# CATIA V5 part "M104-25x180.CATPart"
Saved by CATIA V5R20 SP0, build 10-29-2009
Part number: M104-25x180
Source: Unknown
Bounding box of the stored display mesh (mm): x -12.497 to 12.497, y -12.358 to 12.358, z 0 to 180
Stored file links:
  C:\Users\Utente\Desktop\IO LAVORO\3D X SITO CF\X SITO\M104\M104-25x180.CATPart

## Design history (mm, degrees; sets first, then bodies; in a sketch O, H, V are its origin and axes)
Body1 (main body)
  Solid1 "PartBody": solid without history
